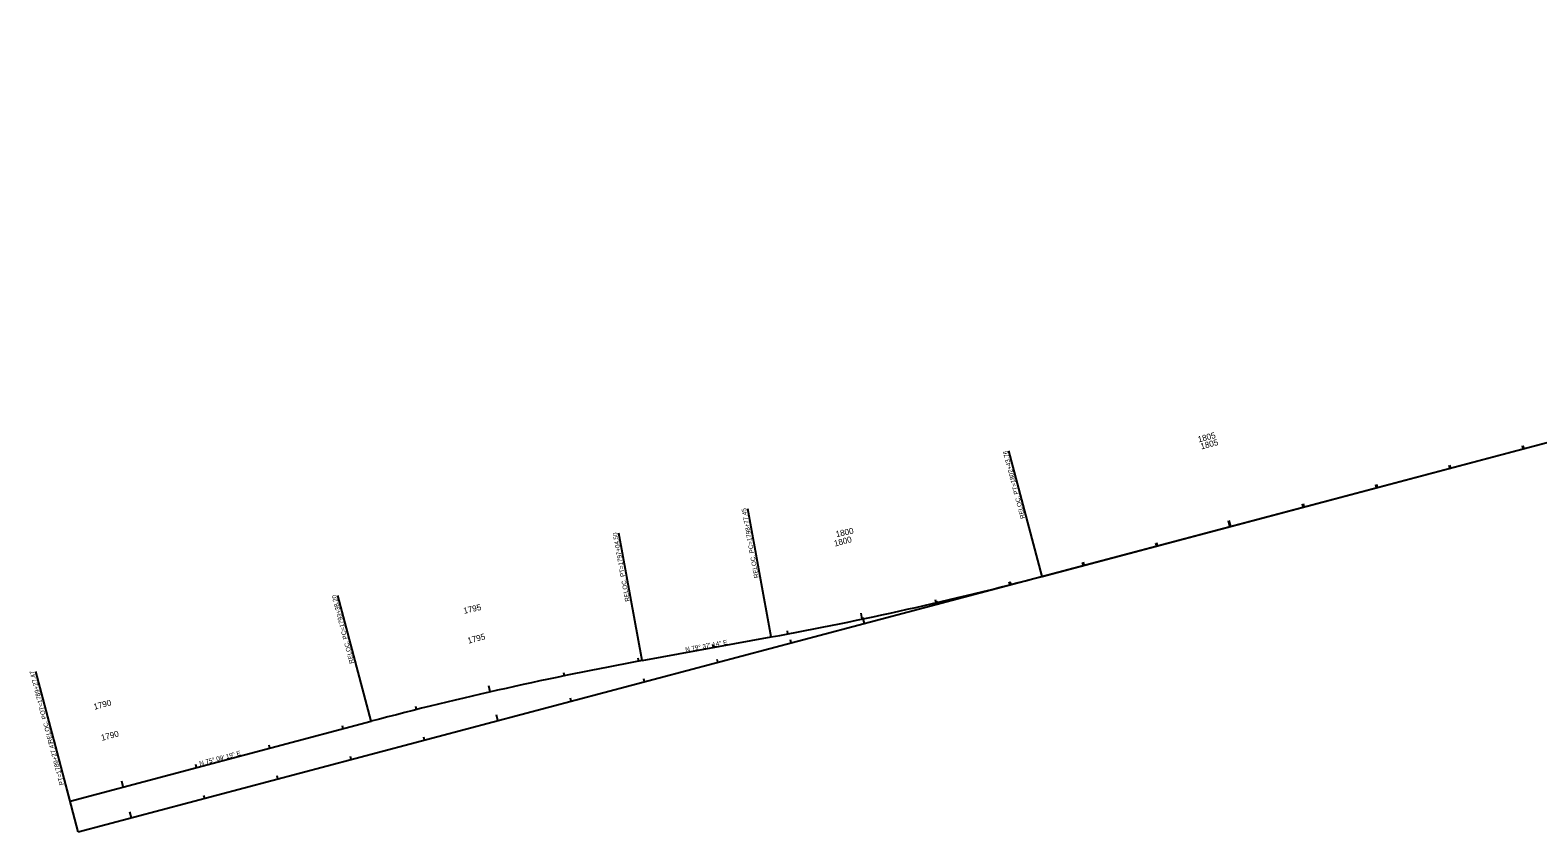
# Model space of a CAD drawing. Extents: x 2106154 to 2121963, y 864504 to 868517.
# Drawn here: x 2110025 to 2112014, y 867153 to 868210 of the extents above; entities that cross this region are included whole.
import ezdxf

# ---------------------------------------------------------------- set-up
doc = ezdxf.new("R2010")
doc.units = 0
for name, color, linetype in [('RD_HC_Cl', 7, 'Continuous'), ('RD_HC_CL_Rel', 7, 'Continuous'), ('RD_HC_Data', 7, 'Continuous'), ('RD_HC_Data_Rel', 7, 'Continuous'), ('RD_HC_Data_Tic', 7, 'Continuous'), ('RD_HC_Data_Tic_Rel', 7, 'Continuous'), ('RD_HC_TX_Rel_Sta50', 7, 'Continuous'), ('RD_HC_TX_Sta50', 7, 'Continuous')]:
    doc.layers.add(name, color=color, linetype=linetype)

msp = doc.modelspace()

# ---------------------------------------------------------------- linework, layer by layer
at = {"layer": 'RD_HC_Cl'}
msp.add_line((2110088.7, 867152.7), (2114077.7, 868210), dxfattribs=at)
at = {"layer": 'RD_HC_CL_Rel'}
for p, q in [((2111359.8, 867489.6), (2112776.4, 867865.1)), ((2110832.3, 867378.5), (2111002.5, 867409.7)), ((2110077.9, 867193.3), (2110475, 867298.6))]:
    msp.add_line(p, q, dxfattribs=at)
for centre, start, end in [((2110155.7, 872032.8), 280.3793, 284.8448), ((2111679.1, 862755.4), 100.3793, 104.8448)]:
    msp.add_arc(centre, 4700, start, end, dxfattribs=at)
at = {"layer": 'RD_HC_Data'}
msp.add_line((2110088.7, 867152.7), (2110056.7, 867273.3), dxfattribs=at)
at = {"layer": 'RD_HC_Data_Rel'}
for p, q in [((2111359.8, 867489.6), (2111316, 867655)), ((2111002.5, 867409.7), (2110971.5, 867578.7)), ((2110832.3, 867378.5), (2110801.5, 867546.8)), ((2110475, 867298.6), (2110430.9, 867464.6)), ((2110077.9, 867193.3), (2110032.6, 867364.4))]:
    msp.add_line(p, q, dxfattribs=at)
at = {"layer": 'RD_HC_Data_Tic'}
for p, q in [((2111995.4, 867658.1), (2111994.4, 867662)), ((2111898.7, 867632.5), (2111897.7, 867636.3)), ((2111802.1, 867606.9), (2111801.1, 867610.7)), ((2111705.4, 867581.2), (2111704.4, 867585.1)), ((2111608.8, 867555.6), (2111606.7, 867563.4)), ((2111512.1, 867530), (2111511.1, 867533.9)), ((2111415.4, 867504.4), (2111414.4, 867508.2)), ((2111318.8, 867478.8), (2111317.7, 867482.6)), ((2111222.1, 867453.1), (2111221.1, 867457)), ((2111125.4, 867427.5), (2111123.4, 867435.3)), ((2111028.8, 867401.9), (2111027.8, 867405.8)), ((2110932.1, 867376.3), (2110931.1, 867380.1)), ((2110835.5, 867350.7), (2110834.4, 867354.5)), ((2110738.8, 867325), (2110737.8, 867328.9)), ((2110642.1, 867299.4), (2110640.1, 867307.1)), ((2110545.5, 867273.8), (2110544.4, 867277.7)), ((2110448.8, 867248.2), (2110447.8, 867252)), ((2110352.1, 867222.6), (2110351.1, 867226.4)), ((2110255.5, 867196.9), (2110254.5, 867200.8)), ((2110158.8, 867171.3), (2110156.8, 867179))]:
    msp.add_line(p, q, dxfattribs=at)
at = {"layer": 'RD_HC_Data_Tic_Rel'}
for p, q in [((2111994.2, 867657.8), (2111993.2, 867661.6)), ((2111897.5, 867632.2), (2111896.5, 867636)), ((2111800.9, 867606.5), (2111799.8, 867610.4)), ((2111704.2, 867580.9), (2111703.2, 867584.8)), ((2111607.5, 867555.3), (2111605.5, 867563)), ((2111510.9, 867529.7), (2111509.8, 867533.5)), ((2111414.2, 867504.1), (2111413.2, 867507.9)), ((2111317.5, 867478.6), (2111316.5, 867482.5)), ((2111220.3, 867454.9), (2111219.4, 867458.8)), ((2111122.7, 867433.3), (2111121.1, 867441.2)), ((2111024.6, 867413.8), (2111023.9, 867417.7)), ((2110926.3, 867395.7), (2110925.6, 867399.7)), ((2110827.9, 867377.7), (2110827.2, 867381.6)), ((2110632, 867337.3), (2110630.3, 867345.1)), ((2110729.8, 867358.6), (2110729, 867362.5)), ((2110534.8, 867314), (2110533.8, 867317.9)), ((2110438, 867288.8), (2110437, 867292.6)), ((2110341.4, 867263.2), (2110340.4, 867267)), ((2110244.7, 867237.5), (2110243.7, 867241.4)), ((2110148.1, 867211.9), (2110146, 867219.6))]:
    msp.add_line(p, q, dxfattribs=at)

# ---------------------------------------------------------------- texts
at = {"layer": 'RD_HC_Data'}
msp.add_text('PT=1789+27.47', height=6, rotation=104.8448, dxfattribs=at).set_placement((2110070.1, 867215.1))
at = {"layer": 'RD_HC_Data_Rel'}
for s, rotation, p in [('RELOC. PT=1802+43.76', 104.8448, (2111337.4, 867566.5)), ('RELOC. PC=1798+77.45', 100.3793, (2110986.1, 867488)), ('RELOC. PT=1797+04.50', 100.3793, (2110816, 867456.9)), ('RELOC. PC=1793+38.20', 104.8448, (2110452.5, 867375.4)), ('N 79%%d 37\' 14" E', 10.3793, (2110889.8, 867390.1)), ('RELOC. POT=1789+27.47', 104.8448, (2110055.5, 867270.1)), ('N 75%%d 09\' 19" E', 14.8448, (2110249.2, 867239.8))]:
    msp.add_text(s, height=6, rotation=rotation, dxfattribs=at).set_placement(p)
at = {"layer": 'RD_HC_TX_Rel_Sta50'}
for s, rotation, p in [('1805', 14.8448, (2111566.3, 867666.2)), ('1800', 11.8732, (2111088.5, 867541.3)), ('1795', 12.8723, (2110597.6, 867440.2)), ('1790', 14.8448, (2110110, 867313.6))]:
    msp.add_text(s, height=8, rotation=rotation, dxfattribs=at).set_placement(p)
at = {"layer": 'RD_HC_TX_Sta50'}
for s, p in [('1805', (2111569.8, 867657)), ('1800', (2111086.5, 867528.9)), ('1795', (2110603.2, 867400.8)), ('1790', (2110119.9, 867272.7))]:
    msp.add_text(s, height=8, rotation=14.8448, dxfattribs=at).set_placement(p)

doc.saveas('drawing.dxf')
